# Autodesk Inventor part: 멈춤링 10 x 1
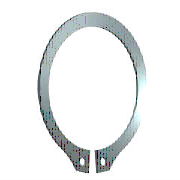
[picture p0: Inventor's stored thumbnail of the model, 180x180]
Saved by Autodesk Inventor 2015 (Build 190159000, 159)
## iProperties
IsCustomPart: 0
Created: 2015-11
Part Number: 멈춤링 10 x 1
Material: 스테인리스강
Description: 리테이닝 링(C형)
Document SubType Name: Modeling
Standard: KS B 1336
Designer: mdu
Standards Organization: KS
Language: ko-KR
Size Designation: 10 x 1
Categories: <MemberInstance><Categories><Category DisplayName="샤프트 부품" InternalName="7f7aeb1f-a693-4053-b835-cee3144e0d98" Mnemonic="SHFT"><Category DisplayName="써클립" Inter
Density: 8.08 g/cm^3
Appearance: 반광택
Mass: 0.434929 g
Surface Area: 1.9243 cm^2
Volume: 0.0538279 cm^3
Author: mdu
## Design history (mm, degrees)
sketch "스케치1"
  geometry: L1 (-6, 0)-(6, 0) reference; L2 (0, 20.189)-(0, -80.536) reference; L3 (-48.09, 0)-(48.09, 0) reference; L4 (-0.3, -9.791)-(-0.3, -12.791); L5 (-0.3, -6.54)-(-0.3, -13.29); L6 (-2.795, 1.6)-(3.672, 1.6); L7 (0.3, -6.54)-(0.3, -13.29); L8 (0.3, -9.791)-(0.3, -12.791); C1 r 0.6 at (-1.2, -11.486); C2 r 0.6 at (1.2, -11.486); A1 r 4.8 centre (0, -5) between (0.3, -9.791) and (-0.3, -9.791); A2 r 6.2 centre (0, -4.6) between (2.988, -10.033) and (-2.988, -10.033); A3 r 7.796 centre (0, -5) between (-1.418, -12.666) and (-0.3, -12.791); A4 r 1.2 centre (-1.2, -11.486) between (-2.383, -11.285) and (-1.418, -12.666); A5 r 1.2 centre (-3.566, -11.084) between (-2.383, -11.285) and (-2.988, -10.033); A6 r 1.2 centre (3.566, -11.084) between (2.988, -10.033) and (2.383, -11.285); A7 r 1.2 centre (1.2, -11.486) between (1.418, -12.666) and (2.383, -11.285); A8 r 7.796 centre (0, -5) between (0.3, -12.791) and (1.418, -12.666)
  constraints: 16 point on circle, 12 end point, 10 centre point, 9 symmetric about line, 5 point on line, 4 tangent, 3 coincident, 2 horizontal, 1 perpendicular, 1 vertical, 5 other
  dimensions: "d0" = 9.6 diameter of A1 (= ND); "d1" = 3 distance of L4.end L4.start (= SRB2); "d6" = 0.3 distance between parallel lines of L2 L5 (= 0.25 x SD5); "d7" = 1.6 distance between parallel lines of L6 L3 (= SRB1); "d8" = 0.4 distance of A1.centre A2.centre (= 0.25 x SRB1); "d9" = 1.2 radius of A4 (= SD5); "d10" = 1.2 radius of A5 (= SD5); "d11" = 0.9 distance from line of L4 A4.centre (= 0.75 x SD5); "d12" = 1.2 diameter of C1 (= SD5); "d13" = 1.2 diameter of C2 (= SD5); "d14" = 5 distance from line of A1.centre L1 (= 0.5 x WD)
extrude "본체" new body sketch "스케치1" distance "d2" = 1 (= SD); taper "d3" = 0 deg
workaxis "Work Axis1"
workplane "Work Plane1"
body "Solid1"
other parameters: "SD" = 1 [user parameter; used in 1 equation term], "SRB1" = 1.6 [user parameter; used in 2 equation terms], "ND" = 9.6 [user parameter; used in 1 equation term], "SRB2" = 3 [user parameter; used in 1 equation term], "SD5" = 1.2 [user parameter; used in 6 equation terms], "d15" = 0, "d16" = 0, "d17" = 0, "d41" = 0, "d42" = 0, "SD3" = 9.3 [user parameter], "WDMAX" = 11 [user parameter]
